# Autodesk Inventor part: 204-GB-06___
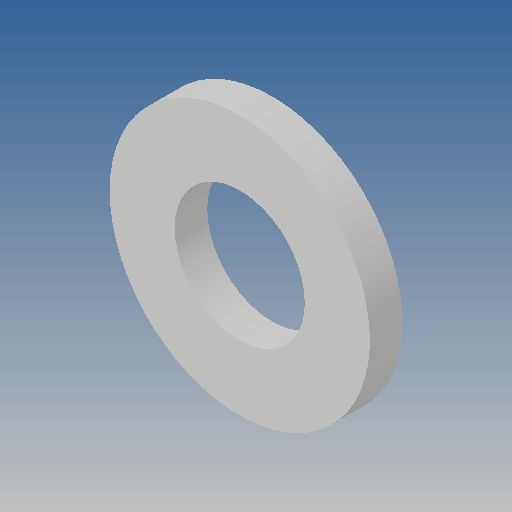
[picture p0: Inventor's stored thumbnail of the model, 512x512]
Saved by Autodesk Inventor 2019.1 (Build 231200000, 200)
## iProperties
Created: 2012-09
Part Number: 204-GB-06___
Material: Ogólny
Document SubType Name: Modeling
Designer: CADENGINEERING4
Density: 1 g/cm^3
Appearance: Domyślna
Author: CADENGINEERING4
Revision Number: ÈÎºÎ
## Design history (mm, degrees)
feature "NONE"
node "Bryła1"
